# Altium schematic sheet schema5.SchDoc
size A3; ApprovedBy: CdB; CheckedBy: CdB; DrawnBy: RT; Engineer: CdB; Organization: Faber Electronics B.V.; Address1: Th. Dobbeweg 1,; Address2: 6883 GN Velp,; Address3: Netherlands; Address4: T: 026-38 46 800; DocumentNumber: 5; Revision: 2.1.4; SheetNumber: 5; SheetTotal: 6; Status: Final; PageSetup: Record=PageOptions|CenterHorizontal=True|CenterVertical=True|PrintScale=1.01|XCorrection=1.00|YCorrection=1.00|PrintKind=1|BorderSize=5000000|LeftOffset=0|BottomOffset=0|Orientation=2|PaperLength=1000|PaperWidth=1000|Scale=100|PaperSource=7|PrintQuality=1200|MediaType=1|DitherType=10|PaperKind=A3 (297 x 420mm)|PrintScaleMode=1
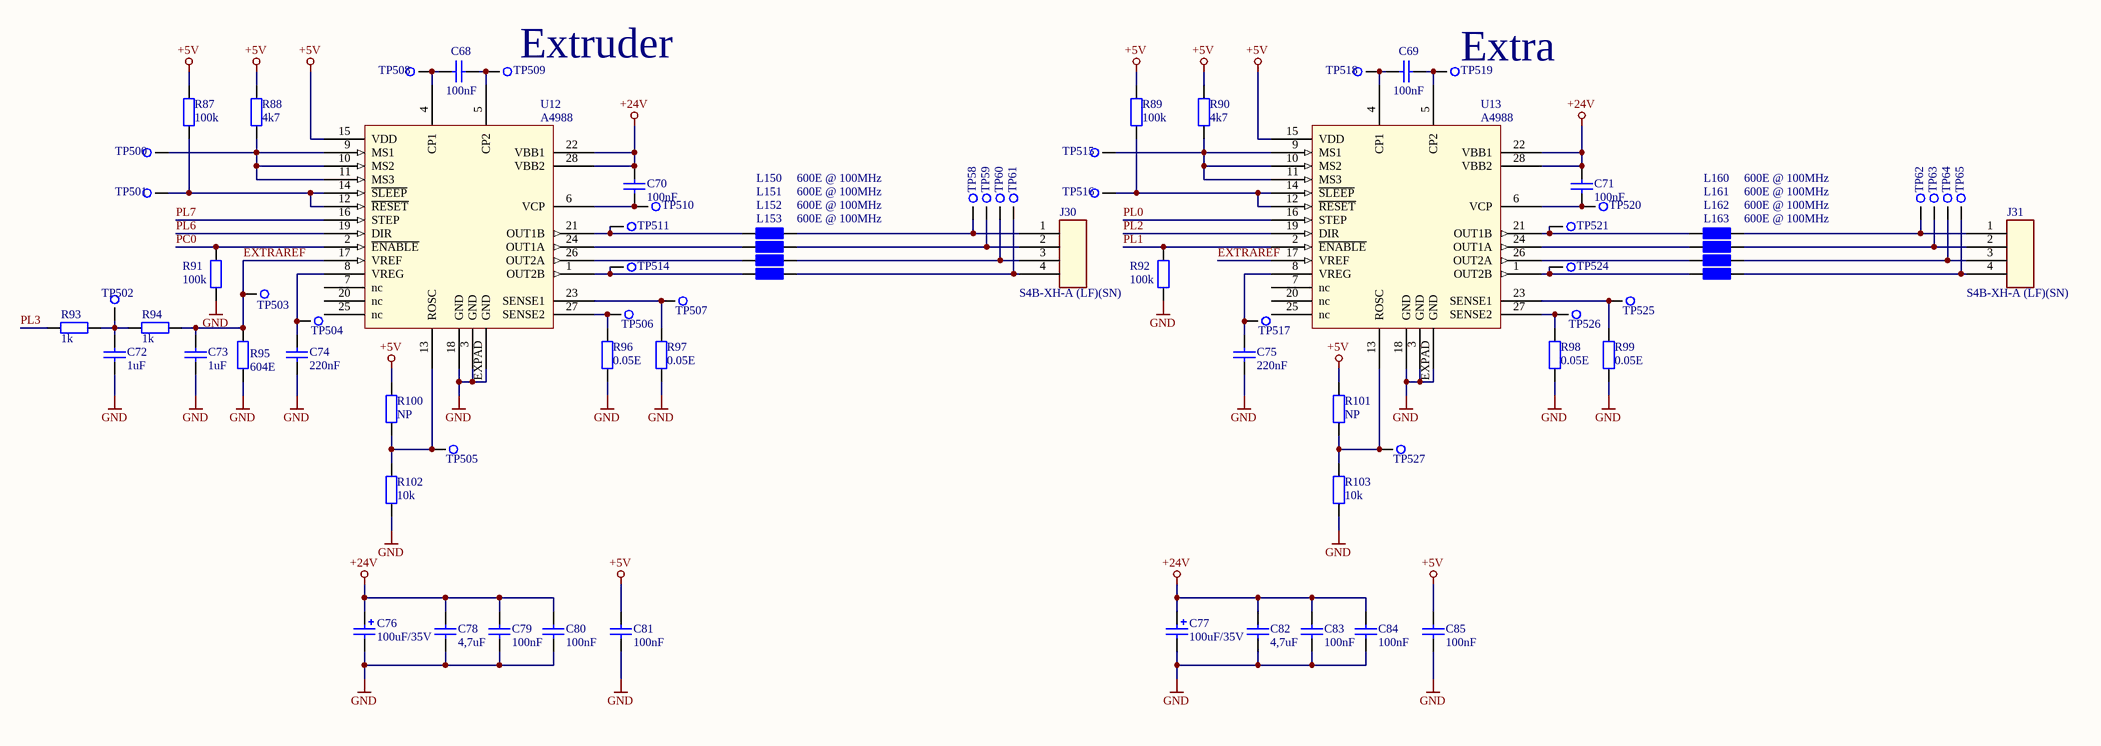
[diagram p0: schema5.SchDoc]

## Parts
C68  100nF  [C0603]
C69  100nF  [C0603]
C70  100nF  [C0603]
C71  100nF  [C0603]
C72  1uF  [C0603]
C73  1uF  [C0603]
C74  220nF  [C0603]
C75  220nF  [C0603]
C76  100uF/35V  [ELCO Case D]
C77  100uF/35V  [ELCO Case D]
C78  4,7uF  [C1206]
C79  100nF  [C0603]
C80  100nF  [C0603]
C81  100nF  [C0603]
C82  4,7uF  [C1206]
C83  100nF  [C0603]
C84  100nF  [C0603]
C85  100nF  [C0603]
J30  S4B-XH-A (LF)(SN)  [S4B-XH-A (LF)(SN)]
J31  S4B-XH-A (LF)(SN)  [S4B-XH-A (LF)(SN)]
L150  600E @ 100MHz  [R1206]
L151  600E @ 100MHz  [R1206]
L152  600E @ 100MHz  [R1206]
L153  600E @ 100MHz  [R1206]
L160  600E @ 100MHz  [R1206]
L161  600E @ 100MHz  [R1206]
L162  600E @ 100MHz  [R1206]
L163  600E @ 100MHz  [R1206]
R87  100k  [R0603]
R88  4k7  [R0603]
R89  100k  [R0603]
R90  4k7  [R0603]
R91  100k  [R0603]
R92  100k  [R0603]
R93  1k  [R0603]
R94  1k  [R0603]
R95  604E  [R0603]
R96  0.05E  [R0805]
R97  0.05E  [R0805]
R98  0.05E  [R0805]
R99  0.05E  [R0805]
R100  NP  [R0603]
R101  NP  [R0603]
R102  10k  [R0603]
R103  10k  [R0603]
TP58  Testpoint  [Testpoint]  (value not drawn)
TP59  Testpoint  [Testpoint]  (value not drawn)
TP60  Testpoint  [Testpoint]  (value not drawn)
TP61  Testpoint  [Testpoint]  (value not drawn)
TP62  Testpoint  [Testpoint]  (value not drawn)
TP63  Testpoint  [Testpoint]  (value not drawn)
TP64  Testpoint  [Testpoint]  (value not drawn)
TP65  Testpoint  [Testpoint]  (value not drawn)
TP500  Testpoint 1mm  [Testpoint 1mm]  (value not drawn)
TP501  Testpoint 1mm  [Testpoint 1mm]  (value not drawn)
TP502  Testpoint 1mm  [Testpoint 1mm]  (value not drawn)
TP503  Testpoint 1mm  [Testpoint 1mm]  (value not drawn)
TP504  Testpoint 1mm  [Testpoint 1mm]  (value not drawn)
TP505  Testpoint 1mm  [Testpoint 1mm]  (value not drawn)
TP506  Testpoint 1mm  [Testpoint 1mm]  (value not drawn)
TP507  Testpoint 1mm  [Testpoint 1mm]  (value not drawn)
TP508  Testpoint 1mm  [Testpoint 1mm]  (value not drawn)
TP509  Testpoint 1mm  [Testpoint 1mm]  (value not drawn)
TP510  Testpoint 1mm  [Testpoint 1mm]  (value not drawn)
TP511  Testpoint 1mm  [Testpoint 1mm]  (value not drawn)
TP514  Testpoint 1mm  [Testpoint 1mm]  (value not drawn)
TP515  Testpoint 1mm  [Testpoint 1mm]  (value not drawn)
TP516  Testpoint 1mm  [Testpoint 1mm]  (value not drawn)
TP517  Testpoint 1mm  [Testpoint 1mm]  (value not drawn)
TP518  Testpoint 1mm  [Testpoint 1mm]  (value not drawn)
TP519  Testpoint 1mm  [Testpoint 1mm]  (value not drawn)
TP520  Testpoint 1mm  [Testpoint 1mm]  (value not drawn)
TP521  Testpoint 1mm  [Testpoint 1mm]  (value not drawn)
TP524  Testpoint 1mm  [Testpoint 1mm]  (value not drawn)
TP525  Testpoint 1mm  [Testpoint 1mm]  (value not drawn)
TP526  Testpoint 1mm  [Testpoint 1mm]  (value not drawn)
TP527  Testpoint 1mm  [Testpoint 1mm]  (value not drawn)
U12  A4988  [QFN50P500X500X100-28-EX]
U13  A4988  [QFN50P500X500X100-28-EX]

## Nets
+5V: C81.2 C85.2 R87.2 R88.2 R89.2 R90.2 R100.2 R101.2 U12.15(VDD) U13.15(VDD)
+24V: C70.2 C71.2 C76.1 C77.1 C78.2 C79.2 C80.2 C82.2 C83.2 C84.2 U12.22(VBB1) U12.28(VBB2) U13.22(VBB1) U13.28(VBB2)
GND: C72.1 C73.1 C74.1 C75.1 C76.2 C77.2 C78.1 C79.1 C80.1 C81.1 C82.1 C83.1 C84.1 C85.1 R91.2 R92.2 R95.1 R96.1 R97.1 R98.1 R99.1 R102.1 R103.1 U12.3(GND) U12.18(GND) U12.EXPAD(GND) U13.3(GND) U13.18(GND) U13.EXPAD(GND)
EXTRAREF: C73.2 R94.2 R95.2 TP503.1 U12.17(VREF) U13.17(VREF)
PC0: R91.1 U12.2(~{ENABLE})
PL0: U13.16(STEP)
PL1: R92.1 U13.2(~{ENABLE})
PL2: U13.19(DIR)
PL3: R93.1
PL6: U12.19(DIR)
PL7: U12.16(STEP)
NetC68_1: C68.1 TP508.1 U12.4(CP1)
NetC68_2: C68.2 TP509.1 U12.5(CP2)
NetC69_1: C69.1 TP518.1 U13.4(CP1)
NetC69_2: C69.2 TP519.1 U13.5(CP2)
NetC70_1: C70.1 TP510.1 U12.6(VCP)
NetC71_1: C71.1 TP520.1 U13.6(VCP)
NetC72_2: C72.2 R93.2 R94.1 TP502.1
NetC74_2: C74.2 TP504.1 U12.8(VREG)
NetC75_2: C75.2 TP517.1 U13.8(VREG)
NetJ30_1: J30.1 L150.2 TP58.1
NetJ30_2: J30.2 L151.2 TP59.1
NetJ30_3: J30.3 L152.2 TP60.1
NetJ30_4: J30.4 L153.2 TP61.1
NetJ31_1: J31.1 L160.2 TP62.1
NetJ31_2: J31.2 L161.2 TP63.1
NetJ31_3: J31.3 L162.2 TP64.1
NetJ31_4: J31.4 L163.2 TP65.1
NetL150_1: L150.1 TP511.1 U12.21(OUT1B)
NetL151_1: L151.1 U12.24(OUT1A)
NetL152_1: L152.1 U12.26(OUT2A)
NetL153_1: L153.1 TP514.1 U12.1(OUT2B)
NetL160_1: L160.1 TP521.1 U13.21(OUT1B)
NetL161_1: L161.1 U13.24(OUT1A)
NetL162_1: L162.1 U13.26(OUT2A)
NetL163_1: L163.1 TP524.1 U13.1(OUT2B)
NetR87_1: R87.1 TP501.1 U12.12(~{RESET}) U12.14(~{SLEEP})
NetR88_1: R88.1 TP500.1 U12.9(MS1) U12.10(MS2) U12.11(MS3)
NetR89_1: R89.1 TP516.1 U13.12(~{RESET}) U13.14(~{SLEEP})
NetR90_1: R90.1 TP515.1 U13.9(MS1) U13.10(MS2) U13.11(MS3)
NetR96_2: R96.2 TP506.1 U12.27(SENSE2)
NetR97_2: R97.2 TP507.1 U12.23(SENSE1)
NetR98_2: R98.2 TP526.1 U13.27(SENSE2)
NetR99_2: R99.2 TP525.1 U13.23(SENSE1)
NetR100_1: R100.1 R102.2 TP505.1 U12.13(ROSC)
NetR101_1: R101.1 R103.2 TP527.1 U13.13(ROSC)

Not connected (* = marked no-connect by the designer): U12 7(nc) 20(nc) 25(nc); U13 7(nc) 20(nc) 25(nc)

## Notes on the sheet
- (near TP509) Extruder
- (near TP519) Extra

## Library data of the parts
C68-C71 C79-C81 C83-C85 = Library_CAP-0002: RO X7R 100nF 10% 50V 0603; Faber ItemCode: 45068500
C72 C73 = Library_CAP-0006: RO X5R 1uF 10% 10V 0603; Faber ItemCode: 36310600
C74 C75 = Library_CAP-0001: RO X7R 220nF 10% 25V  0603; Faber ItemCode: 36126300
C76 C77 = Library_CAP-0004: RO ELCO 100uF 20% 35V CASE-D EEEFP PAN; Faber ItemCode: 36865800
C78 C82 = Library_CAP-0003: RO X7R 4,7uF 10% 50V 1206; Faber ItemCode: 35404600
J30 J31 = Library_CON-0005: RO CONN PR 4p HKS S4B-XH-A (LF)(SN) JST; Mfg: JST (JAPAN SOLDERLESS TERMINALS); Faber ItemCode: 36926500
L150-L153 L160-L163 = Ferriet Bead 600E: FERRIET 742792118 1206 Wurth Elektronik; Mfg: Wurth Elektronics; Mfg code: 1800374
R87 R89 R91 R92 = Library_RES-0005: RO RES 100k0 1% 0,063W  0603; Faber ItemCode: 36257800
R88 R90 = Library_RES-0002: RO RES 4k70 1% 0,063W  0603; Faber ItemCode: 36257400
R93 R94 = Library_RES-0004: RO RES 1k0 1% 0,1W  0603; Faber ItemCode: 34637900
R95 = Library_RES-0018: RO RES 604E 1% 0,063W 0603; Mfg: VISHAY DRALORIC; Mfg code: CRCW0603604RFKEA; Faber ItemCode: 36932600
R96-R99 = Library_RES-0013: RO RES 0E05 1% 0,125W 0805; Mfg: BOURNS; Mfg code: CRL0805-FW-R050ELF; Faber ItemCode: 36925700
R100 R101 = Library_RES-0001
R102 R103 = Library_RES-0001: RO RES 10k0 1% 0,063W  0603; Faber ItemCode: 36084500
TP58-TP65 = Library_MISC-0001: Info: Testpoint, 2mm, round
TP500-TP511 TP514-TP521 TP524-TP527 = Testpoint 1mm: ID: Library_MISC-0001
U12 U13 = Library_ICS-0002: RO IC A4988 QFN-28 ALLEGRO; Mfg code: A4988SETTR-T; Info: DMOS Microstepping Driver with Translator and Overcurrent Protection; Faber ItemCode: 36921600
